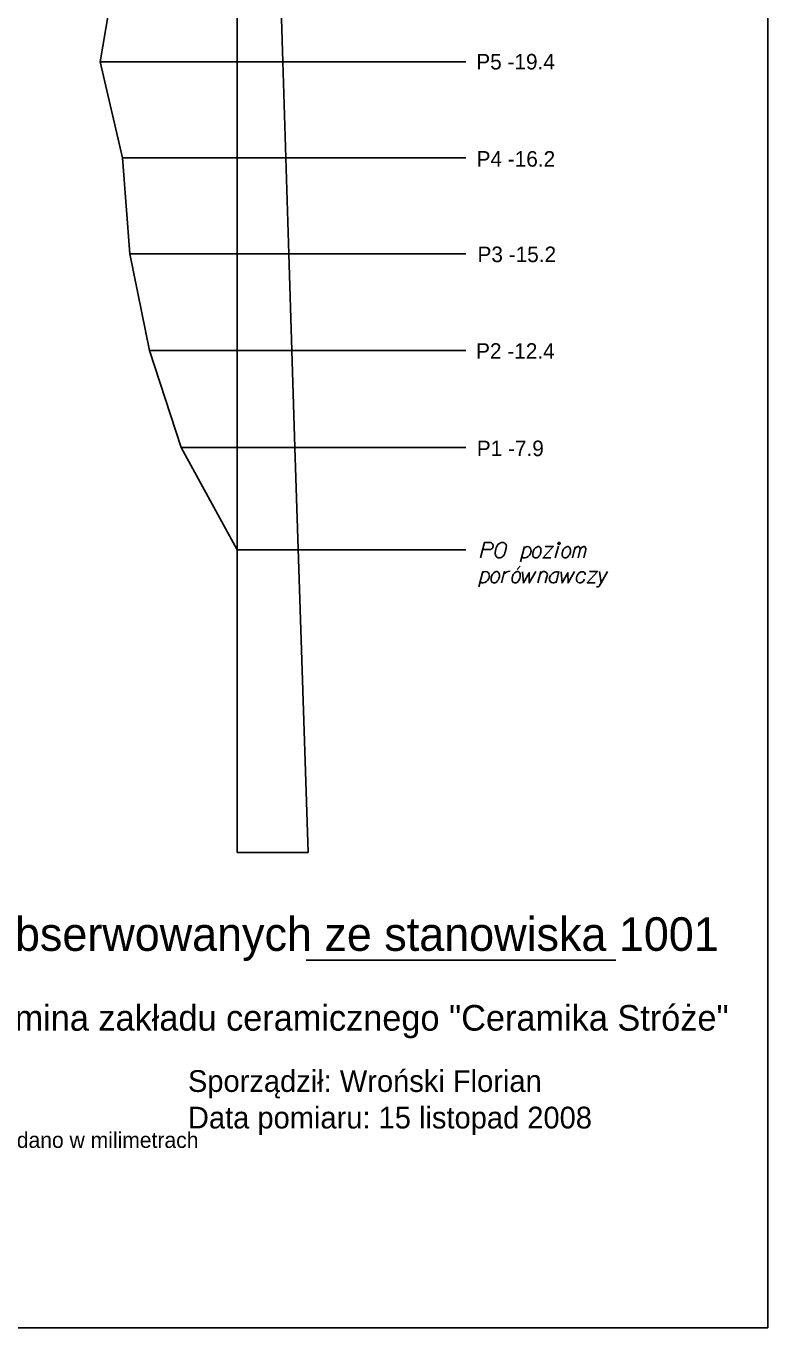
# Model space of a CAD drawing. Extents: x 138 to 6653, y -177 to 1520.
# Drawn here: x 356.39 to 366.89, y 2.29 to 20.71 of the extents above; entities that cross this region are included whole.
import ezdxf

# ---------------------------------------------------------------- set-up
doc = ezdxf.new("R2010")
doc.units = 0
for name, color, linetype in [('15 listopad 2008', 7, 'Continuous'), ('Opisy', 7, 'Continuous'), ('Ramka do drukowania', 7, 'Continuous'), ('Standart wykresów', 7, 'Continuous'), ('Wykresy 4 maj 2008', 7, 'Continuous')]:
    doc.layers.add(name, color=color, linetype=linetype)

msp = doc.modelspace()

# ---------------------------------------------------------------- linework, layer by layer
at = {"layer": '15 listopad 2008'}
msp.add_lwpolyline([(359.38, 13.297), (358.59, 14.742), (358.14, 16.118), (357.86, 17.485), (357.76, 18.843), (357.44, 20.202), (357.68, 21.593), (357.91, 22.995), (357.87, 23.989), (357.72, 24.969), (357.86, 25.428), (357.24, 25.945), (356.86, 26.413), (355.81, 26.981), (355.35, 27.507), (354.84, 27.694), (351.75, 28.392), (349.95, 28.755), (348.15, 29.011)], dxfattribs=at)
at = {"layer": 'Opisy'}
msp.add_line((360.357, 7.488), (364.741, 7.488), dxfattribs=at)
at = {"layer": 'Ramka do drukowania'}
for p, q in [((366.893, 2.285), (366.893, 31.985)), ((345.893, 2.285), (366.893, 2.285))]:
    msp.add_line(p, q, dxfattribs=at)
at = {"layer": 'Standart wykresów'}
for p, q in [((359.38, 9.011), (359.38, 29.095)), ((360.027, 20.202), (359.982, 21.593)), ((359.38, 20.202), (362.617, 20.202)), ((360.069, 18.843), (360.027, 20.202)), ((359.38, 18.843), (362.617, 18.843)), ((360.111, 17.485), (360.069, 18.843)), ((359.38, 17.485), (362.617, 17.485)), ((360.154, 16.118), (360.111, 17.485)), ((359.38, 16.118), (362.617, 16.118)), ((360.199, 14.742), (360.154, 16.118)), ((359.38, 14.742), (358.59, 14.742)), ((359.38, 14.742), (362.617, 14.742)), ((360.386, 9.011), (360.199, 14.742)), ((359.38, 13.297), (362.617, 13.297)), ((359.38, 9.011), (360.386, 9.011))]:
    msp.add_line(p, q, dxfattribs=at)
for points in [[(362.823, 13.181), (362.882, 13.401), (362.956, 13.401), (362.967, 13.399), (362.972, 13.398), (362.982, 13.392), (362.989, 13.387), (362.995, 13.38), (363, 13.372), (363.003, 13.36), (363.005, 13.349), (363.003, 13.341), (363.001, 13.334), (362.998, 13.327), (362.995, 13.321), (362.989, 13.315), (362.982, 13.309), (362.977, 13.306), (362.969, 13.302), (362.96, 13.301), (362.856, 13.301)], [(363.138, 13.401), (363.135, 13.401), (363.124, 13.399), (363.117, 13.398), (363.112, 13.396), (363.104, 13.392), (363.093, 13.387), (363.085, 13.382), (363.076, 13.375), (363.071, 13.368), (363.066, 13.36), (363.06, 13.351), (363.055, 13.341), (363.052, 13.334), (363.048, 13.323), (363.043, 13.306), (363.038, 13.28), (363.034, 13.259), (363.034, 13.24), (363.036, 13.226), (363.043, 13.211), (363.048, 13.202), (363.057, 13.192), (363.067, 13.185), (363.072, 13.183), (363.083, 13.181), (363.092, 13.181), (363.105, 13.183), (363.117, 13.186), (363.126, 13.192), (363.138, 13.2), (363.143, 13.205), (363.15, 13.212), (363.156, 13.219), (363.159, 13.224), (363.163, 13.233), (363.164, 13.237), (363.168, 13.245), (363.171, 13.256), (363.175, 13.266), (363.176, 13.273), (363.178, 13.278), (363.18, 13.285), (363.183, 13.301), (363.185, 13.309), (363.187, 13.318), (363.189, 13.33), (363.19, 13.346), (363.19, 13.351), (363.189, 13.358), (363.187, 13.365), (363.182, 13.375), (363.176, 13.382), (363.171, 13.387), (363.164, 13.392), (363.157, 13.396), (363.152, 13.398), (363.147, 13.399), (363.138, 13.401)], [(363.389, 13.124), (363.448, 13.341)], [(363.443, 13.321), (363.46, 13.335), (363.486, 13.341), (363.507, 13.337), (363.521, 13.327), (363.531, 13.313), (363.538, 13.294), (363.54, 13.276), (363.537, 13.261), (363.531, 13.242), (363.518, 13.221), (363.5, 13.202), (363.474, 13.185), (363.452, 13.181), (363.431, 13.183), (363.408, 13.195)], [(363.637, 13.341), (363.649, 13.341), (363.663, 13.334), (363.677, 13.315), (363.679, 13.306), (363.68, 13.297), (363.68, 13.29), (363.68, 13.264), (363.675, 13.247), (363.667, 13.226), (363.656, 13.209), (363.639, 13.193), (363.623, 13.181), (363.597, 13.181), (363.587, 13.185), (363.576, 13.193), (363.571, 13.202), (363.564, 13.223), (363.564, 13.254), (363.568, 13.264), (363.575, 13.287), (363.582, 13.299), (363.585, 13.306), (363.602, 13.325), (363.62, 13.335), (363.637, 13.341)], [(363.741, 13.344), (363.854, 13.344), (363.71, 13.181), (363.821, 13.181)], [(363.883, 13.181), (363.928, 13.349)], [(363.932, 13.401), (363.94, 13.401), (363.945, 13.398), (363.951, 13.391), (363.951, 13.382), (363.945, 13.375), (363.94, 13.372), (363.932, 13.372), (363.926, 13.375), (363.921, 13.382), (363.921, 13.391), (363.926, 13.398), (363.932, 13.401)], [(364.053, 13.341), (364.065, 13.341), (364.079, 13.334), (364.093, 13.315), (364.094, 13.306), (364.096, 13.297), (364.096, 13.29), (364.096, 13.264), (364.091, 13.247), (364.082, 13.226), (364.072, 13.209), (364.055, 13.193), (364.039, 13.181), (364.013, 13.181), (364.003, 13.185), (363.992, 13.193), (363.987, 13.202), (363.98, 13.223), (363.98, 13.254), (363.984, 13.264), (363.99, 13.287), (363.997, 13.299), (364.001, 13.306), (364.018, 13.325), (364.036, 13.335), (364.053, 13.341)], [(364.126, 13.181), (364.165, 13.339)], [(364.155, 13.297), (364.164, 13.316), (364.172, 13.327), (364.183, 13.334), (364.193, 13.339), (364.2, 13.342), (364.21, 13.342), (364.214, 13.341), (364.221, 13.334), (364.228, 13.325), (364.233, 13.309), (364.235, 13.301), (364.243, 13.316), (364.254, 13.327), (364.264, 13.334), (364.275, 13.339), (364.283, 13.342), (364.292, 13.342), (364.299, 13.341), (364.304, 13.334), (364.309, 13.325), (364.314, 13.309), (364.316, 13.301), (364.287, 13.181)], [(364.205, 13.181), (364.235, 13.301)], [(362.8, 12.771), (362.859, 12.987)], [(362.854, 12.968), (362.871, 12.982), (362.897, 12.987), (362.918, 12.984), (362.932, 12.973), (362.942, 12.96), (362.949, 12.941), (362.951, 12.923), (362.947, 12.908), (362.942, 12.889), (362.928, 12.868), (362.911, 12.849), (362.885, 12.831), (362.862, 12.828), (362.842, 12.83), (362.819, 12.842)], [(363.048, 12.987), (363.06, 12.987), (363.074, 12.98), (363.088, 12.961), (363.089, 12.953), (363.091, 12.944), (363.091, 12.937), (363.091, 12.911), (363.086, 12.894), (363.077, 12.873), (363.067, 12.856), (363.049, 12.84), (363.034, 12.828), (363.008, 12.828), (362.998, 12.831), (362.987, 12.84), (362.982, 12.849), (362.975, 12.87), (362.975, 12.901), (362.978, 12.911), (362.985, 12.934), (362.992, 12.946), (362.996, 12.953), (363.013, 12.972), (363.03, 12.982), (363.048, 12.987)], [(363.12, 12.828), (363.164, 12.993)], [(363.153, 12.953), (363.162, 12.96), (363.181, 12.973), (363.202, 12.982), (363.217, 12.987), (363.242, 12.993)], [(363.344, 12.987), (363.356, 12.987), (363.37, 12.98), (363.384, 12.961), (363.385, 12.953), (363.387, 12.944), (363.387, 12.937), (363.387, 12.911), (363.382, 12.894), (363.373, 12.873), (363.363, 12.856), (363.346, 12.84), (363.33, 12.828), (363.304, 12.828), (363.294, 12.831), (363.283, 12.84), (363.278, 12.849), (363.271, 12.87), (363.271, 12.901), (363.275, 12.911), (363.282, 12.934), (363.288, 12.946), (363.292, 12.953), (363.309, 12.972), (363.327, 12.982), (363.344, 12.987)], [(363.387, 13.064), (363.344, 13.015)], [(363.417, 12.986), (363.431, 12.828), (363.514, 12.972), (363.515, 12.828), (363.607, 12.989)], [(363.637, 12.828), (363.68, 12.987)], [(363.67, 12.949), (363.675, 12.958), (363.682, 12.968), (363.687, 12.973), (363.694, 12.98), (363.701, 12.984), (363.709, 12.987), (363.718, 12.989), (363.725, 12.989), (363.734, 12.987), (363.741, 12.984), (363.748, 12.98), (363.754, 12.975), (363.761, 12.968), (363.765, 12.963), (363.768, 12.956), (363.772, 12.947), (363.741, 12.828)], [(363.931, 12.973), (363.919, 12.982), (363.89, 12.982), (363.872, 12.979), (363.841, 12.961), (363.815, 12.93), (363.803, 12.897), (363.801, 12.88), (363.803, 12.866), (363.808, 12.854), (363.819, 12.84), (363.831, 12.831), (363.85, 12.828), (363.864, 12.83), (363.877, 12.831), (363.897, 12.842)], [(363.935, 12.987), (363.893, 12.828)], [(363.964, 12.986), (363.978, 12.828), (364.061, 12.972), (364.063, 12.828), (364.155, 12.989)], [(364.307, 12.941), (364.305, 12.961), (364.297, 12.975), (364.286, 12.982), (364.265, 12.986), (364.246, 12.986), (364.222, 12.97), (364.203, 12.944), (364.189, 12.918), (364.184, 12.899), (364.184, 12.87), (364.186, 12.859), (364.193, 12.845), (364.208, 12.831), (364.226, 12.828), (364.245, 12.83), (364.255, 12.833), (364.278, 12.849), (364.295, 12.878)], [(364.368, 12.991), (364.48, 12.991), (364.336, 12.828), (364.447, 12.828)], [(364.621, 12.989), (364.532, 12.828), (364.504, 12.781), (364.498, 12.778), (364.489, 12.774), (364.472, 12.771), (364.465, 12.771)], [(364.51, 12.987), (364.532, 12.828)]]:
    msp.add_lwpolyline(points, dxfattribs=at)
at = {"layer": 'Wykresy 4 maj 2008'}
for p, q in [((359.38, 20.202), (357.44, 20.202)), ((359.38, 18.843), (357.76, 18.843)), ((359.38, 17.485), (357.86, 17.485)), ((359.38, 16.118), (358.14, 16.118))]:
    msp.add_line(p, q, dxfattribs=at)

# ---------------------------------------------------------------- texts
at = {"layer": 'Opisy'}
for s, height, p in [('Wykres wychyleń osi komina obserwowanych ze stanowiska 1001', 0.47516, (347.585, 7.621)), ('Badanie pionowości i prostoliniowości komina zakładu ceramicznego "Ceramika Stróże"', 0.36281, (347.466, 6.492)), ('Sporządził: Wroński Florian', 0.30766, (358.684, 5.625)), ('Data pomiaru: 15 listopad 2008', 0.30766, (358.684, 5.108)), ('Wartości wychyleń komina dla poszczególnych poziomów podano w milimetrach', 0.22315, (348.218, 4.833))]:
    msp.add_text(s, height=height, dxfattribs=at).set_placement(p)
at = {"layer": 'Wykresy 4 maj 2008'}
for s, p in [('P5 -19.4', (362.765, 20.092)), ('P4 -16.2', (362.769, 18.717)), ('P3 -15.2', (362.782, 17.366)), ('P2 -12.4', (362.762, 15.999)), ('P1 -7.9', (362.772, 14.621))]:
    msp.add_text(s, height=0.22, dxfattribs=at).set_placement(p)

doc.saveas('drawing.dxf')
